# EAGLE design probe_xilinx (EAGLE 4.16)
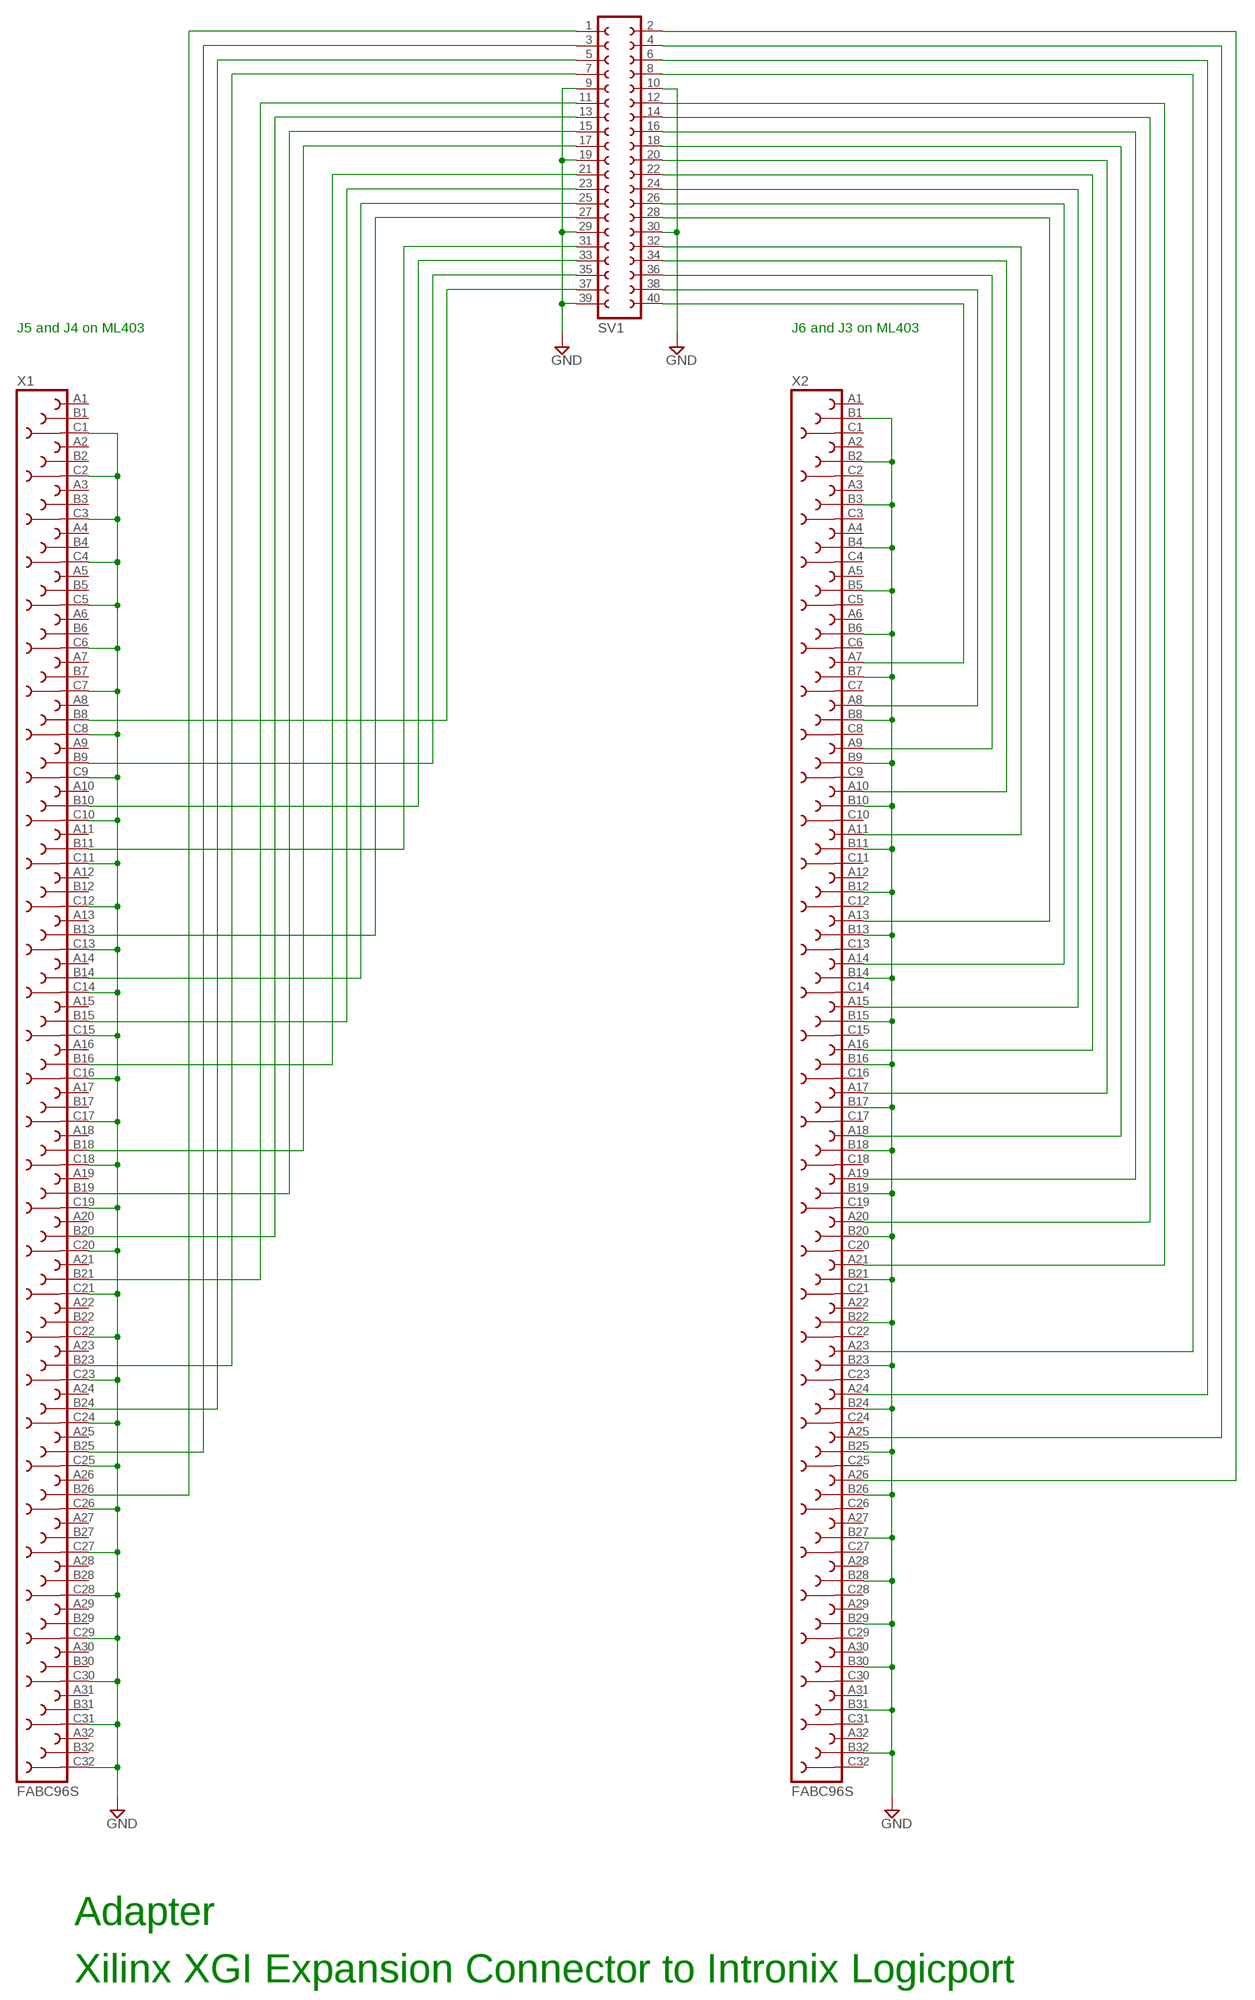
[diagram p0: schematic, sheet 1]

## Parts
SV1  FE20-2  [FE20-2]
X1  FABC96S  [FABC96S]
X2  FABC96S  [FABC96S]

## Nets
GND: SV1.9 SV1.10 SV1.19 SV1.29 SV1.30 SV1.39 X1.C1 X1.C2 X1.C3 X1.C4 X1.C5 X1.C6 X1.C7 X1.C8 X1.C9 X1.C10 X1.C11 X1.C12 X1.C13 X1.C14 X1.C15 X1.C16 X1.C17 X1.C18 X1.C19 X1.C20 X1.C21 X1.C22 X1.C23 X1.C24 X1.C25 X1.C26 X1.C27 X1.C28 X1.C29 X1.C30 X1.C31 X1.C32 X2.B1 X2.B2 X2.B3 X2.B4 X2.B5 X2.B6 X2.B7 X2.B8 X2.B9 X2.B10 X2.B11 X2.B12 X2.B13 X2.B14 X2.B15 X2.B16 X2.B17 X2.B18 X2.B19 X2.B20 X2.B21 X2.B22 X2.B23 X2.B24 X2.B25 X2.B26 X2.B27 X2.B28 X2.B29 X2.B30 X2.B31 X2.B32
N$10: SV1.23 X1.B15
N$11: SV1.25 X1.B14
N$12: SV1.27 X1.B13
N$13: SV1.31 X1.B11
N$14: SV1.33 X1.B10
N$15: SV1.35 X1.B9
N$16: SV1.37 X1.B8
N$34: SV1.1 X1.B26
N$35: SV1.3 X1.B25
N$36: SV1.5 X1.B24
N$37: SV1.7 X1.B23
N$39: SV1.11 X1.B21
N$40: SV1.13 X1.B20
N$41: SV1.15 X1.B19
N$42: SV1.17 X1.B18
N$44: SV1.21 X1.B16
N$55: SV1.2 X2.A26
N$56: SV1.4 X2.A25
N$57: SV1.6 X2.A24
N$58: SV1.8 X2.A23
N$60: SV1.12 X2.A21
N$61: SV1.14 X2.A20
N$62: SV1.16 X2.A19
N$63: SV1.18 X2.A18
N$64: SV1.20 X2.A17
N$65: SV1.22 X2.A16
N$66: SV1.24 X2.A15
N$67: SV1.26 X2.A14
N$68: SV1.28 X2.A13
N$70: SV1.32 X2.A11
N$71: SV1.34 X2.A10
N$72: SV1.36 X2.A9
N$73: SV1.38 X2.A8
N$74: SV1.40 X2.A7
Unconnected: X1.A1 X1.A2 X1.A3 X1.A4 X1.A5 X1.A6 X1.A7 X1.A8 X1.A9 X1.A10 X1.A11 X1.A12 X1.A13 X1.A14 X1.A15 X1.A16 X1.A17 X1.A18 X1.A19 X1.A20 X1.A21 X1.A22 X1.A23 X1.A24 X1.A25 X1.A26 X1.A27 X1.A28 X1.A29 X1.A30 X1.A31 X1.A32 X1.B1 X1.B2 X1.B3 X1.B4 X1.B5 X1.B6 X1.B7 X1.B12 X1.B17 X1.B22 X1.B27 X1.B28 X1.B29 X1.B30 X1.B31 X1.B32 X2.A1 X2.A2 X2.A3 X2.A4 X2.A5 X2.A6 X2.A12 X2.A22 X2.A27 X2.A28 X2.A29 X2.A30 X2.A31 X2.A32 X2.C1 X2.C2 X2.C3 X2.C4 X2.C5 X2.C6 X2.C7 X2.C8 X2.C9 X2.C10 X2.C11 X2.C12 X2.C13 X2.C14 X2.C15 X2.C16 X2.C17 X2.C18 X2.C19 X2.C20 X2.C21 X2.C22 X2.C23 X2.C24 X2.C25 X2.C26 X2.C27 X2.C28 X2.C29 X2.C30 X2.C31 X2.C32

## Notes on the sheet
- J5 and J4 on ML403 | J6 and J3 on ML403
- Adapter
- Xilinx XGI Expansion Connector to Intronix Logicport

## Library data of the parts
SV1 = con-lsta:FE20-2: FEMALE HEADER
X1 X2 = con-vg:FABC96S: CONNECTOR female, 96 pins, block, type C, rows ABC, grid 2.54 mm

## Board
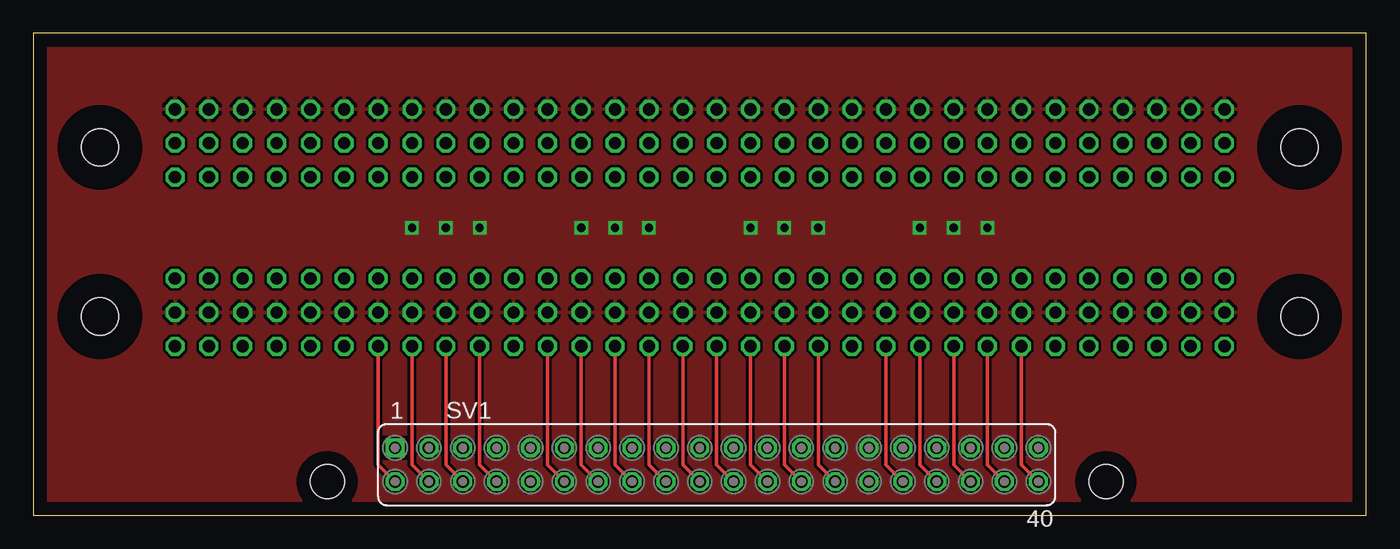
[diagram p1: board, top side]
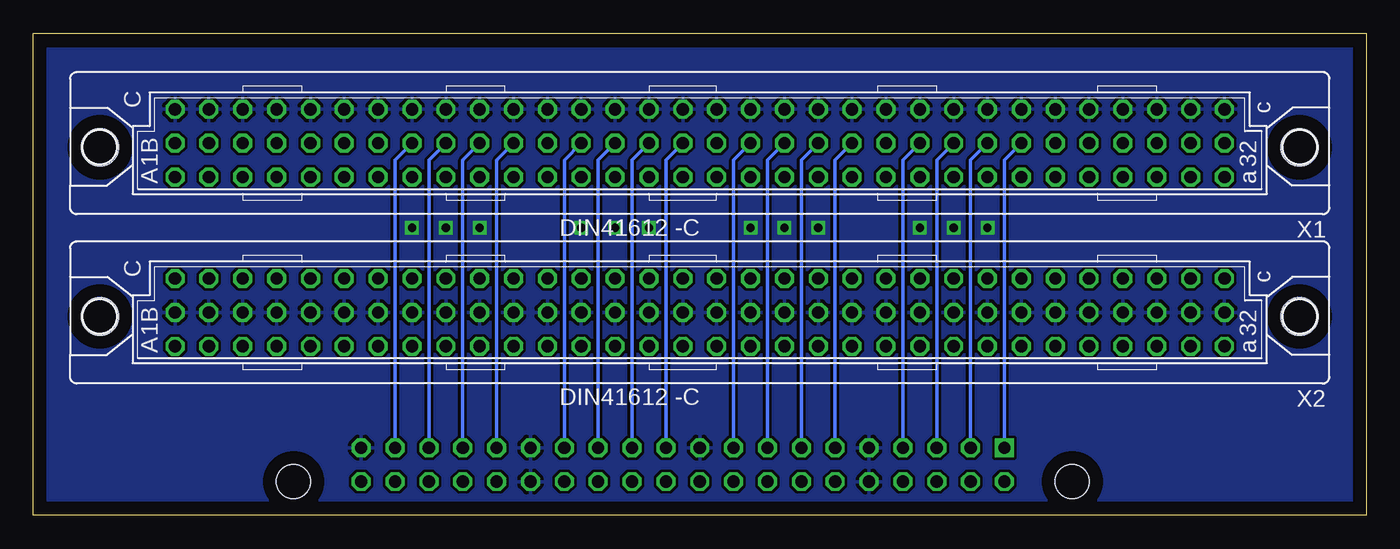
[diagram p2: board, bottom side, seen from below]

Size 100 x 36.19 mm. Coordinates in mm from the lower left corner, seen from the top.
Outline: 0,0 100,0 100,36.19 0,36.19 0,0
Copper layers (1*16): Top 0.035mm / dielectric 1.5mm / Bottom 0.035mm
Design rules "default": minimum track width 10mil, minimum drill 24mil, track to track 8mil, track to pad 8mil, pad to pad 8mil, via to via 8mil, smd to smd 8mil, copper to edge 40mil, drill to drill 8mil, minimum pad ring 10mil, minimum via ring 8mil, stop-mask expansion 4mil, vias tented up to drill 0mil, thermal gap 10mil
Holes 2.54 mm at 22.06,2.54 80.48,2.54

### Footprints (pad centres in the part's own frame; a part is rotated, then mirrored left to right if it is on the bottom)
FE20-2 = drill 0.914 square: 1 -24.13,1.27 | drill 0.914 octagon: 2 -24.13,-1.27; 3 -21.59,1.27; 4 -21.59,-1.27; 5 -19.05,1.27; 6 -19.05,-1.27; 7 -16.51,1.27; 8 -16.51,-1.27; 9 -13.97,1.27; 10 -13.97,-1.27; 11 -11.43,1.27; 12 -11.43,-1.27; 13 -8.89,1.27; 14 -8.89,-1.27; 15 -6.35,1.27; 16 -6.35,-1.27; 17 -3.81,1.27; 18 -3.81,-1.27; 19 -1.27,1.27; 20 -1.27,-1.27; 21 1.27,1.27; 22 1.27,-1.27; 23 3.81,1.27; 24 3.81,-1.27; 25 6.35,1.27; 26 6.35,-1.27; 27 8.89,1.27; 28 8.89,-1.27; 29 11.43,1.27; 30 11.43,-1.27; 31 13.97,1.27; 32 13.97,-1.27; 33 16.51,1.27; 34 16.51,-1.27; 35 19.05,1.27; 36 19.05,-1.27; 37 21.59,1.27; 38 21.59,-1.27; 39 24.13,1.27; 40 24.13,-1.27
FABC96S = drill 0.914 octagon: A1 -2.54,39.37; A2 -2.54,36.83; A3 -2.54,34.29; A4 -2.54,31.75; A5 -2.54,29.21; A6 -2.54,26.67; A7 -2.54,24.13; A8 -2.54,21.59; A9 -2.54,19.05; A10 -2.54,16.51; A11 -2.54,13.97; A12 -2.54,11.43; A13 -2.54,8.89; A14 -2.54,6.35; A15 -2.54,3.81; A16 -2.54,1.27; A17 -2.54,-1.27; A18 -2.54,-3.81; A19 -2.54,-6.35; A20 -2.54,-8.89; A21 -2.54,-11.43; A22 -2.54,-13.97; A23 -2.54,-16.51; A24 -2.54,-19.05; A25 -2.54,-21.59; A26 -2.54,-24.13; A27 -2.54,-26.67; A28 -2.54,-29.21; A29 -2.54,-31.75; A30 -2.54,-34.29; A31 -2.54,-36.83; A32 -2.54,-39.37; B1 0,39.37; B2 0,36.83; B3 0,34.29; B4 0,31.75; B5 0,29.21; B6 0,26.67; B7 0,24.13; B8 0,21.59; B9 0,19.05; B10 0,16.51; B11 0,13.97; B12 0,11.43; B13 0,8.89; B14 0,6.35; B15 0,3.81; B16 0,1.27; B17 0,-1.27; B18 0,-3.81; B19 0,-6.35; B20 0,-8.89; B21 0,-11.43; B22 0,-13.97; B23 0,-16.51; B24 0,-19.05; B25 0,-21.59; B26 0,-24.13; B27 0,-26.67; B28 0,-29.21; B29 0,-31.75; B30 0,-34.29; B31 0,-36.83; B32 0,-39.37; C1 2.54,39.37; C2 2.54,36.83; C3 2.54,34.29; C4 2.54,31.75; C5 2.54,29.21; C6 2.54,26.67; C7 2.54,24.13; C8 2.54,21.59; C9 2.54,19.05; C10 2.54,16.51; C11 2.54,13.97; C12 2.54,11.43; C13 2.54,8.89; C14 2.54,6.35; C15 2.54,3.81; C16 2.54,1.27; C17 2.54,-1.27; C18 2.54,-3.81; C19 2.54,-6.35; C20 2.54,-8.89; C21 2.54,-11.43; C22 2.54,-13.97; C23 2.54,-16.51; C24 2.54,-19.05; C25 2.54,-21.59; C26 2.54,-24.13; C27 2.54,-26.67; C28 2.54,-29.21; C29 2.54,-31.75; C30 2.54,-34.29; C31 2.54,-36.83; C32 2.54,-39.37 | hole 2.794: -0.305,45.009; -0.305,-45.009

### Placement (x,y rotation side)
SV1  51.27,3.81 0 top
X1  50,27.94 90 bottom
X2  50,15.24 90 bottom

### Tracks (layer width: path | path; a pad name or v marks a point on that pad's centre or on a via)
GND  (via drill 0.61)
  other vias: 28.41,21.59 30.95,21.59 33.49,21.59 41.11,21.59 43.65,21.59 46.19,21.59 53.81,21.59 56.35,21.59 58.89,21.59 66.51,21.59 69.05,21.59 71.59,21.59
  pour Top: 0.47,35.55 99.53,35.55 99.53,8.88 83.02,8.88 83.02,0.63 0.47,0.63
  pour Bottom (isolate 0.063): 82.39,9.52 99.53,9.52 99.53,0.63 82.39,0.63
  pour Top (isolate 0.063): 82.39,9.52 99.53,9.52 99.53,0.63 82.39,0.63
  pour Bottom: 0.47,35.55 99.53,35.55 99.53,8.88 83.02,8.88 83.02,0.63 0.47,0.63
N$10
  Bottom 0.254: SV1.23 55.08,26.67 X1.B15
N$11
  Bottom 0.254: SV1.25 57.62,26.67 X1.B14
N$12
  Bottom 0.254: SV1.27 60.16,26.67 X1.B13
N$13
  Bottom 0.254: SV1.31 65.24,26.67 X1.B11
N$14
  Bottom 0.254: SV1.33 67.78,26.67 X1.B10
N$15
  Bottom 0.254: SV1.35 70.32,26.67 X1.B9
N$16
  Bottom 0.254: SV1.37 72.86,26.67 X1.B8
N$34
  Bottom 0.254: SV1.1 27.14,26.67 X1.B26
N$35
  Bottom 0.254: SV1.3 29.68,26.67 X1.B25
N$36
  Bottom 0.254: SV1.5 32.22,26.67 X1.B24
N$37
  Bottom 0.254: SV1.7 34.76,26.67 X1.B23
N$39
  Bottom 0.254: SV1.11 39.84,26.67 X1.B21
N$40
  Bottom 0.254: SV1.13 42.38,26.67 X1.B20
N$41
  Bottom 0.254: SV1.15 44.92,26.67 X1.B19
N$42
  Bottom 0.254: SV1.17 47.46,26.67 X1.B18
N$44
  Bottom 0.254: SV1.21 52.54,26.67 X1.B16
N$55
  Top 0.254: SV1.2 25.87,3.81 X2.A26
N$56
  Top 0.254: SV1.4 28.41,3.81 X2.A25
N$57
  Top 0.254: SV1.6 30.95,3.81 X2.A24
N$58
  Top 0.254: SV1.8 33.49,3.81 X2.A23
N$60
  Top 0.254: SV1.12 38.57,3.81 X2.A21
N$61
  Top 0.254: SV1.14 41.11,3.81 X2.A20
N$62
  Top 0.254: SV1.16 43.65,3.81 X2.A19
N$63
  Top 0.254: SV1.18 46.19,3.81 X2.A18
N$64
  Top 0.254: SV1.20 48.73,3.81 X2.A17
N$65
  Top 0.254: SV1.22 51.27,3.81 X2.A16
N$66
  Top 0.254: SV1.24 53.81,3.81 X2.A15
N$67
  Top 0.254: SV1.26 56.35,3.81 X2.A14
N$68
  Top 0.254: SV1.28 58.89,3.81 X2.A13
N$70
  Top 0.254: SV1.32 63.97,3.81 X2.A11
N$71
  Top 0.254: SV1.34 66.51,3.81 X2.A10
N$72
  Top 0.254: SV1.36 69.05,3.81 X2.A9
N$73
  Top 0.254: SV1.38 71.59,3.81 X2.A8
N$74
  Top 0.254: SV1.40 74.13,3.81 X2.A7

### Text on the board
tRestrict: Xilinx - | Logicport
bRestrict: Xilinx - | Logicport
